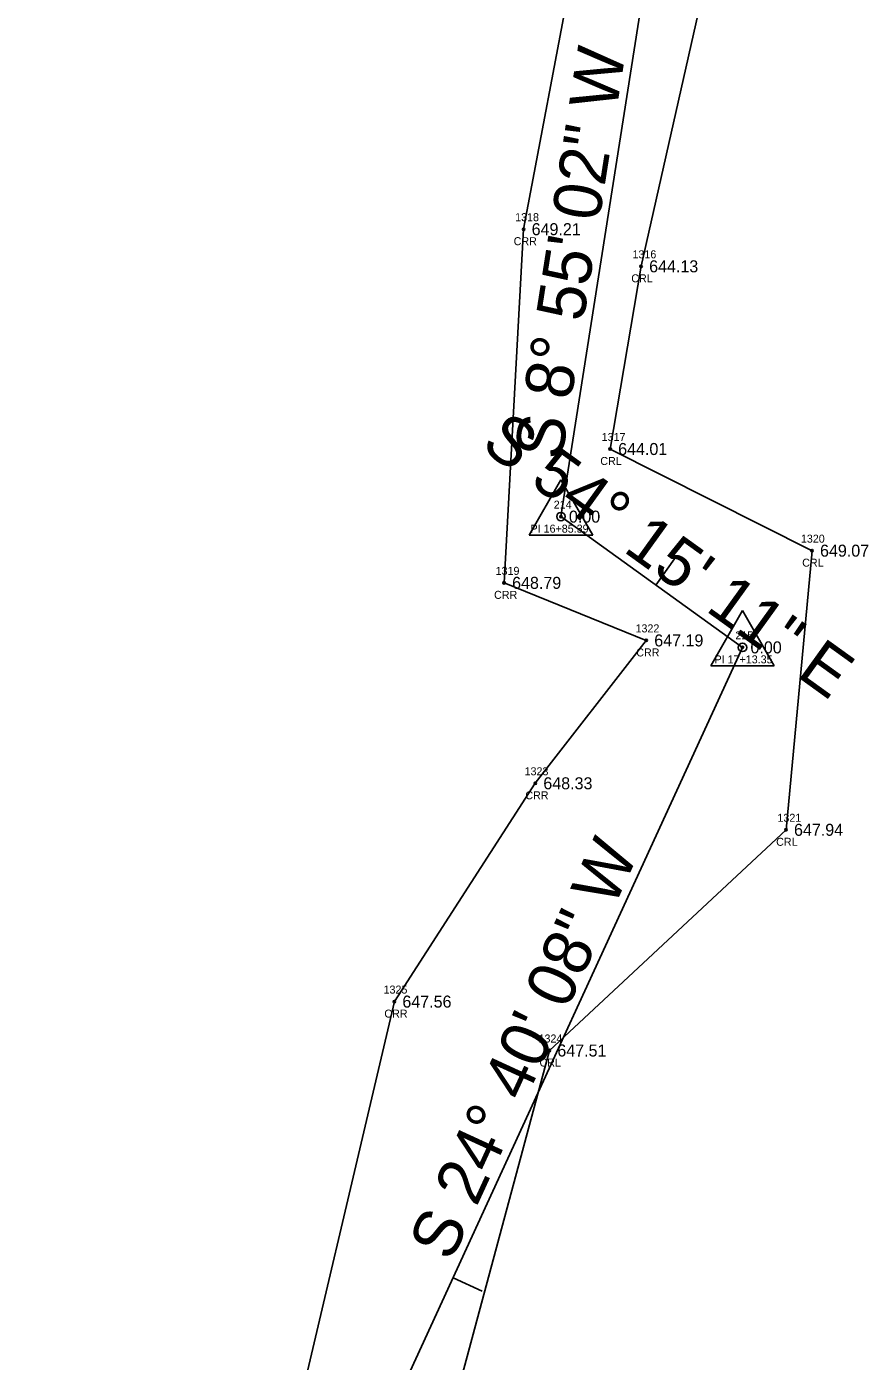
# Model space of a CAD drawing. Extents: x 1655137 to 1657928, y 1003994 to 1005407.
# Drawn here: x 1656296.7 to 1656401.9, y 1004398.2 to 1004565 of the extents above; entities that cross this region are included whole.
import ezdxf

# ---------------------------------------------------------------- set-up
doc = ezdxf.new("R2010")
doc.units = 0
for name, color, linetype in [('RD_EX_H2O', 7, 'Continuous'), ('RD_EX_H2O_txCode', 7, 'Continuous'), ('RD_EX_TX_H2O_ELEV', 7, 'Continuous'), ('RD_HC_Cl', 7, 'Continuous'), ('RD_HC_Data', 7, 'Continuous'), ('RD_HC_Data_Tic', 7, 'Continuous'), ('RD_HC_Survey_ELEV', 7, 'Continuous'), ('RD_HC_txCode', 7, 'Continuous'), ('RD_SMD_Locator', 7, 'Continuous')]:
    doc.layers.add(name, color=color, linetype=linetype)

msp = doc.modelspace()

# ---------------------------------------------------------------- linework, layer by layer
at = {"layer": 'RD_EX_H2O'}
for points in [[(1656368.16, 1004641.29), (1656361.32, 1004615.92), (1656361.94, 1004600.44), (1656360.19, 1004590.3), (1656364.85, 1004571.61), (1656358.83, 1004539.66), (1656356.39, 1004495.48), (1656374.15, 1004488.29), (1656360.29, 1004470.44), (1656342.68, 1004443.17), (1656328, 1004380.72), (1656370, 1004347.54), (1656371.38, 1004313.92), (1656341.06, 1004297.9), (1656327.33, 1004287.25), (1656316.16, 1004265.33), (1656323.68, 1004217.95), (1656315.99, 1004185.06), (1656305.45, 1004150.63), (1656296.74, 1004101.67)], [(1656396.09, 1004633.07), (1656388.01, 1004605.83), (1656383, 1004600.69), (1656372.14, 1004591.42), (1656381.32, 1004569.61), (1656373.51, 1004535.02), (1656369.64, 1004512.2), (1656394.86, 1004499.5), (1656391.61, 1004464.63), (1656362.04, 1004437.06), (1656349.14, 1004389.09), (1656389.79, 1004361.99), (1656392.68, 1004307.58), (1656360.76, 1004281.14), (1656349.55, 1004259.28), (1656348.46, 1004221.09), (1656343.48, 1004177.61), (1656328.72, 1004142.77), (1656319.4, 1004085.87)]]:
    msp.add_lwpolyline(points, dxfattribs=at)
at = {"layer": 'RD_HC_Cl'}
for p, q in [((1656373.8, 1004569.48), (1656363.49, 1004503.75)), ((1656363.49, 1004503.75), (1656386.17, 1004487.42)), ((1656386.17, 1004487.42), (1656339.03, 1004384.77))]:
    msp.add_line(p, q, dxfattribs=at)
at = {"layer": 'RD_HC_Data'}
for p, q in [((1656359.52, 1004501.45), (1656363.49, 1004508.33)), ((1656363.49, 1004508.33), (1656367.46, 1004501.45)), ((1656359.52, 1004501.45), (1656367.46, 1004501.45)), ((1656382.2, 1004485.13), (1656386.18, 1004492.01)), ((1656386.18, 1004492.01), (1656390.14, 1004485.13)), ((1656382.2, 1004485.13), (1656390.14, 1004485.13))]:
    msp.add_line(p, q, dxfattribs=at)
for centre in [(1656363.49, 1004503.75), (1656386.17, 1004487.42)]:
    msp.add_circle(centre, 0.529, dxfattribs=at)
at = {"layer": 'RD_HC_Data_Tic'}
for p, q in [((1656375.34, 1004495.21), (1656377.68, 1004498.46)), ((1656350.01, 1004408.67), (1656353.64, 1004407))]:
    msp.add_line(p, q, dxfattribs=at)
at = {"layer": 'RD_SMD_Locator'}
for centre in [(1656358.83, 1004539.66), (1656373.51, 1004535.02), (1656369.64, 1004512.2), (1656363.49, 1004503.75), (1656394.86, 1004499.5), (1656356.39, 1004495.48), (1656374.15, 1004488.29), (1656386.17, 1004487.42), (1656360.29, 1004470.44), (1656391.61, 1004464.63), (1656342.68, 1004443.17), (1656362.04, 1004437.06)]:
    msp.add_circle(centre, 0.15, dxfattribs=at)

# ---------------------------------------------------------------- texts
at = {"layer": 'RD_EX_H2O_txCode'}
for s, p in [('1318', (1656357.77, 1004540.66)), ('CRR', (1656357.58, 1004537.66)), ('1316', (1656372.43, 1004536.02)), ('CRL', (1656372.28, 1004533.02)), ('1317', (1656368.58, 1004513.2)), ('CRL', (1656368.41, 1004510.2)), ('1320', (1656393.47, 1004500.5)), ('CRL', (1656393.63, 1004497.5)), ('1319', (1656355.33, 1004496.48)), ('CRR', (1656355.14, 1004493.48)), ('1322', (1656372.81, 1004489.29)), ('CRR', (1656372.9, 1004486.29)), ('1323', (1656358.95, 1004471.44)), ('CRR', (1656359.04, 1004468.44)), ('1321', (1656390.54, 1004465.63)), ('CRL', (1656390.38, 1004462.63)), ('1325', (1656341.33, 1004444.17)), ('CRR', (1656341.43, 1004441.17)), ('1324', (1656360.69, 1004438.06)), ('CRL', (1656360.81, 1004435.06))]:
    msp.add_text(s, height=1, dxfattribs=at).set_placement(p)
at = {"layer": 'RD_EX_TX_H2O_ELEV'}
for s, p in [('649.21', (1656359.83, 1004538.91)), ('644.13', (1656374.51, 1004534.27)), ('644.01', (1656370.64, 1004511.45)), ('649.07', (1656395.86, 1004498.75)), ('648.79', (1656357.39, 1004494.73)), ('647.19', (1656375.15, 1004487.54)), ('648.33', (1656361.29, 1004469.69)), ('647.94', (1656392.61, 1004463.88)), ('647.56', (1656343.68, 1004442.42)), ('647.51', (1656363.04, 1004436.31))]:
    msp.add_text(s, height=1.5, dxfattribs=at).set_placement(p)
at = {"layer": 'RD_HC_Data'}
for s, rotation, p in [('S 8%%d 55\' 02" W', 81.0827, (1656363.57, 1004510.71)), ('S 54%%d 15\' 11" E', 324.2531, (1656353.31, 1004512.31)), ('S 24%%d 40\' 08" W', 65.3312, (1656349.76, 1004410.54))]:
    msp.add_text(s, height=6, rotation=rotation, dxfattribs=at).set_placement(p)
at = {"layer": 'RD_HC_Survey_ELEV'}
for p in [(1656364.49, 1004503), (1656387.17, 1004486.67)]:
    msp.add_text('0.00', height=1.5, dxfattribs=at).set_placement(p)
at = {"layer": 'RD_HC_txCode'}
for s, p in [('214', (1656362.59, 1004504.75)), ('PI 16+85.39', (1656359.69, 1004501.75)), ('215', (1656385.28, 1004488.42)), ('PI 17+13.35', (1656382.68, 1004485.42))]:
    msp.add_text(s, height=1, dxfattribs=at).set_placement(p)

doc.saveas('drawing.dxf')
